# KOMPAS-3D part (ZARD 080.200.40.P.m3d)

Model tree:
1. Операция без истории:6  (labels: C:\Program Files\ASCON\KOMPAS-3D V13\Sys\graphic.lyt)

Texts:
  ЗАРД 080.200.40-ХХ.Р
  ООО "ИК Энерпред-Ярдос"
